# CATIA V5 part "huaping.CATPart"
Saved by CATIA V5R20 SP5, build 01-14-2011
Part number: 花瓶
Material "Chessboard": density 2500 kg/m3
Bounding box of the stored display mesh (mm): x -24.995 to 24.995, y -40.858 to 24.97, z -0.76 to 115.683
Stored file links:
  E:\huaping.CATPart
  C:\Program Files\Dassault Systemes\B20\intel_a\startup\materials\Catalog.CATMaterial
  C:\Program Files\Dassault Systemes\B20\intel_a\startup\materials\yellow_env_512x512.jpg
  C:\Program Files\Dassault Systemes\B20\intel_a\startup\materials\chessboard.jpg
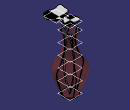
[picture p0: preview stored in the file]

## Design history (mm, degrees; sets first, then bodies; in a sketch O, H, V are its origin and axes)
Body1 (main body)
  Plane1: type Offset, RefPlane xy-plane, Offset 20
  Plane2: type Offset, RefPlane Plane1, Offset 20
  Plane3: type Offset, RefPlane Plane2, Offset 20
  Plane4: type Offset, RefPlane Plane3, Offset 20
  Plane5: type Offset, RefPlane Plane4, Offset 20
  Sketch1 on xy-plane, origin (0, 0, 0), H (1, 0, 0), V (0, 1, 0)
    circle A1 centre (0, 0) radius 12.5
    radius A1 = 12.5
  Sketch2 on Plane1, origin (0, 0, 20), H (1, 0, 0), V (0, 1, 0)
    circle A1 centre (0, 0) radius 20
    radius A1 = 20
  Sketch3 on Plane2, origin (0, 0, 40), H (1, 0, 0), V (0, 1, 0)
    circle A1 centre (0, 0) radius 25
    radius A1 = 25
  Sketch4 on Plane3, origin (0, 0, 60), H (1, 0, 0), V (0, 1, 0)
    circle A1 centre (0, 0) radius 15
    radius A1 = 15
  Sketch5 on Plane4, origin (0, 0, 80), H (1, 0, 0), V (0, 1, 0)
    circle A1 centre (0, 0) radius 10
    radius A1 = 10
  Sketch6 on Plane5, origin (0, 0, 100), H (1, 0, 0), V (0, 1, 0)
    circle A1 centre (0, 0) radius 12.5
    radius A1 = 12.5
  Loft1: solid, Sections (Sketch1; Sketch2; Sketch3; Sketch4; Sketch5; Sketch6)
  Shell1: ExtOffset 0, Face face of Loft1, IntOffset 1
Body2, material "Chessboard"
  Sketch7 on yz-plane, origin (0, 0, 0), H (0, 1, 0), V (0, 0, 1)
    spline S1 through (0, 0) (-10.0589, 28.8209) (-4.4533, 84.9129) (0, 113.6834)
    point P1 (0, 0)
    point P2 (0, 113.6834)
    coincidence: P1 O, P2 V
  Plane6: type Equation, A 0, B 0, C 1, Length 20, RefPoint Sketch7.P2
  Sketch8 on Plane6, origin (0, 0, 113.6834), H (1, 0, 0), V (0, 1, 0)
    circle A1 centre (0, 0) radius 1
    radius A1 = 1
  Rib1: profile Sketch8, centre curve Sketch7
  Sketch9 on Plane6, origin (0, 0, 113.6834), H (1, 0, 0), V (0, 1, 0)
    spline S1 through (1.4063, 7.2309) (10.1957, 1.9733) (6.9143, -5.8546) (-3.8673, -11.4626) (-10.3129, -1.8822) (-11.8364, 5.1279) (1.4063, 7.2309)
    point P1 (1.4063, 7.2309)
    point P2 (1.4063, 7.2309)
    coincidence: P1 P2
  Pad1: profile Sketch9, direction (0, 0, 1), length 2
  Sketch10 on yz-plane, origin (0, 0, 0), H (0, 1, 0), V (0, 0, 1)
    spline S1 through (0, 0) (7.2341, 54.3269) (0, 86.7218) (-25.2598, 108.9837)
    point P1 (0, 0)
    point P2 (0, 86.7218)
    coincidence: P1 O, P2 V
  Plane7: type Equation, A 0, B 0, C 1, Length 20, RefPoint vertex of Sketch10
  Sketch11 on Plane7, origin (0, 0, 108.9837), H (1, 0, 0), V (0, 1, 0)
    circle A1 centre (0, -25.4945) radius 1
    point P1 (0, -25.4945)
    radius A1 = 1
    coincidence: P1 V
  Rib2: profile Sketch11, centre curve Sketch10
  Sketch12 on Plane7, origin (0, 0, 108.9837), H (1, 0, 0), V (0, 1, 0)
    spline S1 through (-11.9014, -19.5227) (4.6371, -14.6252) (9.877, -22.9509) (13.9707, -31.9295) (1.8534, -40.7449) (-6.989, -37.1535) (-19.7613, -38.133) (-19.7613, -29.3176) (-18.2875, -21.8082) (-11.9014, -19.5227)
    point P1 (-11.9014, -19.5227)
    point P2 (-11.9014, -19.5227)
    coincidence: P1 P2
  Pad2: profile Sketch12, direction (0, 0, 1), length 2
